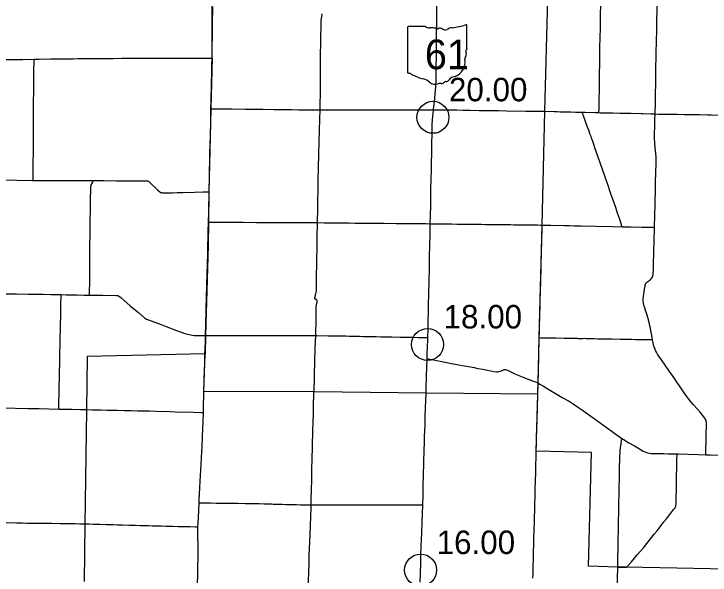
# Model space of a CAD drawing. Extents: x 1815539 to 1947826, y 273303 to 993194.
# Drawn here: x 1859353 to 1891996, y 939932 to 966222 of the extents above; entities that cross this region are included whole.
import ezdxf

# ---------------------------------------------------------------- set-up
doc = ezdxf.new("R2010")
doc.units = 0
for name, color, linetype in [('Default', 7, 'Continuous'), ('GM_X_County', 7, 'Continuous'), ('GM_X_County_Road', 7, 'Continuous'), ('GM_X_State_Route', 7, 'Continuous'), ('GM_X_Township', 7, 'Continuous'), ('GM_X_Township_Road', 7, 'Continuous'), ('SC_Shading3', 7, 'Continuous')]:
    doc.layers.add(name, color=color, linetype=linetype)

msp = doc.modelspace()

# ---------------------------------------------------------------- linework, layer by layer
at = {"layer": 'Default'}
for centre in [(1879002, 961378), (1878750, 950736), (1878424, 940166)]:
    msp.add_circle(centre, 750, dxfattribs=at)
at = {"layer": 'GM_X_County'}
msp.add_lwpolyline([(1855618, 964050), (1860298, 964101), (1862894, 964131), (1865546, 964151), (1868643, 964155), (1868654, 967077)], dxfattribs=at)
at = {"layer": 'GM_X_County_Road'}
for points in [[(1889424, 961538), (1889434, 962041), (1889441, 962402), (1889451, 963025), (1889459, 963534), (1889476, 964387), (1889485, 964945), (1889494, 965470), (1889503, 965962), (1889509, 966356), (1889517, 966733), (1889520, 966850)], [(1873708, 961725), (1873709, 961763), (1873716, 962074), (1873723, 962419), (1873727, 962615), (1873729, 962763), (1873731, 962878), (1873730, 963121), (1873729, 963301), (1873731, 963760), (1873732, 963957), (1873733, 964121), (1873736, 964432), (1873741, 964744), (1873749, 965219), (1873758, 965580), (1873761, 965760), (1873765, 965924), (1873772, 966006), (1873787, 966104), (1873814, 966232)], [(1868507, 957892), (1868508, 957985), (1868512, 958149), (1868517, 958378), (1868522, 958591), (1868529, 958936), (1868537, 959280), (1868545, 959706), (1868564, 960494), (1868580, 961199), (1868592, 961781)], [(1868592, 961781), (1868710, 961779), (1869580, 961768), (1870203, 961762), (1870531, 961757), (1870728, 961755), (1871023, 961753), (1871564, 961746), (1871991, 961742), (1872368, 961737), (1872696, 961735), (1873056, 961731), (1873679, 961725), (1873708, 961725)], [(1873585, 956443), (1873586, 956522), (1873597, 957030), (1873606, 957522), (1873614, 957899), (1873627, 958407), (1873639, 959030), (1873654, 959637), (1873668, 960227), (1873694, 961293), (1873708, 961725)], [(1873708, 961725), (1873925, 961725), (1874171, 961725), (1874400, 961725), (1874728, 961723), (1875040, 961721), (1875351, 961721), (1875696, 961724), (1876204, 961725), (1876483, 961726), (1876860, 961726), (1877139, 961727), (1877533, 961729), (1877959, 961730), (1878370, 961731), (1878730, 961731), (1878944, 961732), (1879031, 961735)], [(1879031, 961735), (1879064, 961735), (1879238, 961734), (1879550, 961729), (1880124, 961721), (1880403, 961717), (1880747, 961712), (1881174, 961704), (1881338, 961703), (1881584, 961698), (1881813, 961694), (1882059, 961692), (1882453, 961686), (1883355, 961673), (1883568, 961670), (1884011, 961664), (1884153, 961662)], [(1884153, 961662), (1884224, 961661), (1884683, 961649), (1884962, 961641), (1885257, 961632), (1885470, 961628), (1885683, 961622), (1885929, 961617), (1886003, 961615)], [(1886003, 961615), (1886142, 961612), (1886602, 961599), (1886785, 961597)], [(1886785, 961597), (1886848, 961596), (1887192, 961590), (1887438, 961582), (1887766, 961576), (1887979, 961573), (1888291, 961566), (1888832, 961553), (1889225, 961541), (1889305, 961540), (1889424, 961538)], [(1889391, 956223), (1889396, 956427), (1889399, 956591), (1889406, 956870), (1889414, 957214), (1889420, 957411), (1889433, 957936), (1889445, 958362), (1889457, 958772), (1889468, 959231), (1889469, 959411), (1889466, 959510), (1889452, 959690), (1889429, 959951), (1889412, 960180), (1889397, 960409), (1889393, 960540), (1889394, 960655), (1889402, 960901), (1889413, 961261), (1889424, 961538)], [(1889424, 961538), (1889576, 961533), (1889771, 961530), (1889984, 961529), (1890296, 961523), (1890476, 961521), (1890788, 961517), (1891263, 961507), (1891493, 961503), (1891870, 961495), (1892050, 961493)], [(1857510, 958468), (1857774, 958464), (1858381, 958450), (1859497, 958428), (1860219, 958415), (1860263, 958416)], [(1860263, 958416), (1860530, 958418), (1860648, 958417)], [(1860648, 958417), (1860798, 958416)], [(1860798, 958416), (1861285, 958413), (1861958, 958413), (1862450, 958411), (1862943, 958412), (1863078, 958412)], [(1863078, 958412), (1863583, 958411), (1864157, 958409), (1864698, 958408), (1865141, 958408), (1865552, 958407), (1865585, 958403), (1865618, 958396), (1865649, 958384), (1865677, 958366), (1865716, 958334), (1866089, 957988), (1866198, 957889), (1866237, 957861), (1866266, 957848), (1866297, 957840), (1866345, 957835), (1866476, 957837), (1866788, 957847), (1867000, 957854), (1867279, 957861), (1867821, 957876), (1868231, 957888), (1868411, 957892), (1868460, 957892), (1868507, 957892)], [(1868479, 956461), (1868488, 956919), (1868495, 957263), (1868503, 957624), (1868507, 957804), (1868507, 957892)], [(1868336, 951151), (1868350, 951655), (1868367, 952311), (1868372, 952508), (1868381, 952869), (1868400, 953541), (1868414, 954033), (1868438, 954984), (1868451, 955394), (1868459, 955722), (1868466, 956017), (1868479, 956461)], [(1873504, 951153), (1873507, 951263), (1873522, 951820), (1873526, 952181), (1873526, 952427), (1873531, 952509), (1873543, 952590), (1873576, 952734), (1873580, 952767), (1873579, 952783), (1873573, 952798), (1873563, 952811), (1873550, 952819), (1873504, 952838), (1873490, 952847), (1873479, 952859), (1873471, 952873), (1873466, 952889), (1873465, 952905), (1873466, 952921), (1873473, 952970), (1873501, 953082), (1873508, 953113), (1873523, 953177), (1873537, 953258), (1873542, 953324), (1873545, 953471), (1873549, 954029), (1873554, 954406), (1873557, 954668), (1873567, 955308), (1873574, 955751), (1873585, 956443)], [(1889186, 951564), (1889176, 951616), (1889143, 951760), (1889078, 951997), (1889044, 952106), (1888991, 952278), (1888936, 952450), (1888897, 952576), (1888877, 952655), (1888867, 952720), (1888863, 952785), (1888863, 952866), (1888872, 952996), (1888883, 953094), (1888918, 953321), (1888945, 953466), (1888959, 953530), (1888975, 953576), (1888991, 953604), (1889010, 953630), (1889034, 953653), (1889072, 953683), (1889167, 953746), (1889205, 953777), (1889240, 953812), (1889269, 953851), (1889292, 953894), (1889310, 953940), (1889319, 953972), (1889326, 954020), (1889332, 954102), (1889336, 954217), (1889343, 954462), (1889347, 954626), (1889355, 954921), (1889358, 955052), (1889363, 955216), (1889370, 955445), (1889374, 955642), (1889376, 955739), (1889386, 956018), (1889391, 956223)], [(1857535, 953123), (1857638, 953122), (1858590, 953112), (1859475, 953106), (1860033, 953098), (1860279, 953094), (1860722, 953087), (1861083, 953078), (1861561, 953071)], [(1861561, 953071), (1861804, 953066), (1862313, 953057), (1862625, 953053), (1862901, 953050)], [(1862901, 953050), (1863117, 953047), (1863527, 953043), (1864150, 953037), (1864199, 953033), (1864230, 953026), (1864258, 953013), (1864298, 952985), (1864359, 952931), (1864811, 952550), (1865212, 952211), (1865474, 951987), (1865525, 951946), (1865567, 951919), (1865612, 951899), (1866261, 951664), (1866491, 951578), (1866983, 951394), (1867244, 951296), (1867369, 951255), (1867496, 951221), (1867720, 951169), (1867801, 951156), (1867883, 951150), (1868113, 951149), (1868336, 951151)], [(1889295, 950966), (1889276, 951068), (1889201, 951487), (1889186, 951564)], [(1868310, 950179), (1868312, 950245), (1868329, 950852), (1868336, 951131), (1868336, 951151)], [(1873420, 948399), (1873426, 948591), (1873444, 949115), (1873451, 949345), (1873467, 949902), (1873486, 950558), (1873504, 951153)], [(1891793, 945572), (1891794, 945623), (1891802, 945902), (1891808, 946148), (1891811, 946295), (1891812, 946393), (1891815, 946524), (1891820, 946688), (1891823, 946819), (1891826, 947032), (1891825, 947098), (1891818, 947146), (1891804, 947193), (1891783, 947238), (1891758, 947280), (1891709, 947345), (1891527, 947557), (1891387, 947718), (1891225, 947903), (1891107, 948039), (1891003, 948166), (1890904, 948297), (1890782, 948471), (1890690, 948607), (1890534, 948838), (1890441, 948973), (1890338, 949121), (1890263, 949229), (1890097, 949473), (1889864, 949810), (1889639, 950132), (1889538, 950281), (1889477, 950379), (1889439, 950452), (1889400, 950542), (1889362, 950650), (1889341, 950729), (1889312, 950874), (1889295, 950966)], [(1868262, 948387), (1868281, 949097), (1868291, 949491), (1868302, 949884), (1868310, 950179)], [(1878728, 950072), (1878772, 950063), (1879110, 949997), (1879578, 949908), (1879949, 949836), (1880223, 949784), (1880384, 949754), (1880674, 949700), (1880932, 949650), (1881110, 949616), (1881335, 949574), (1881561, 949530), (1881851, 949473), (1881980, 949451), (1882013, 949449), (1882045, 949452), (1882093, 949464), (1882171, 949490), (1882246, 949522), (1882306, 949550), (1882337, 949560), (1882370, 949564), (1882402, 949562), (1882434, 949554), (1882494, 949527), (1882805, 949379), (1882957, 949317), (1883185, 949226), (1883629, 949054), (1883859, 948965), (1883918, 948938), (1883935, 948928)], [(1883920, 948423), (1883923, 948503), (1883924, 948585), (1883927, 948678), (1883930, 948781), (1883935, 948928)], [(1883935, 948928), (1884017, 948879), (1884184, 948775), (1884438, 948624), (1884664, 948490), (1885061, 948259), (1885389, 948072), (1885529, 947987), (1885774, 947821), (1886016, 947651), (1886256, 947481), (1886564, 947263), (1886671, 947186), (1886844, 947062), (1887017, 946936), (1887576, 946534), (1887803, 946372), (1887861, 946335)], [(1868239, 947536), (1868241, 947589), (1868248, 947851), (1868262, 948387)], [(1873289, 943219), (1873295, 943443), (1873306, 943951), (1873315, 944361), (1873327, 944968), (1873335, 945279), (1873351, 946017), (1873370, 946657), (1873384, 947132), (1873394, 947460), (1873401, 947739), (1873405, 947903), (1873420, 948399)], [(1883841, 945540), (1883841, 945543), (1883843, 945641), (1883846, 945734), (1883847, 945803), (1883848, 945863), (1883849, 945901), (1883850, 945959), (1883852, 946010), (1883854, 946068), (1883856, 946113), (1883857, 946159), (1883858, 946235), (1883859, 946286), (1883861, 946382), (1883863, 946474), (1883864, 946519), (1883871, 946699), (1883877, 946847), (1883878, 946929), (1883881, 947060), (1883886, 947175), (1883889, 947306), (1883892, 947421), (1883897, 947585), (1883900, 947716), (1883907, 947978), (1883912, 948137), (1883915, 948257), (1883918, 948355), (1883920, 948423)], [(1858837, 947762), (1860001, 947739), (1860542, 947729), (1861455, 947708)], [(1861455, 947708), (1861510, 947707), (1862067, 947697), (1862477, 947688), (1862762, 947682)], [(1862762, 947682), (1863002, 947677), (1863429, 947669), (1863724, 947662), (1864019, 947656), (1864216, 947653), (1864527, 947645), (1864855, 947638), (1865150, 947633), (1865708, 947620), (1866019, 947611), (1866675, 947590), (1866921, 947584), (1867774, 947557), (1868151, 947542), (1868200, 947538), (1868239, 947536)], [(1868039, 943315), (1868046, 943443), (1868077, 944017), (1868093, 944328), (1868137, 945114), (1868155, 945458), (1868181, 945933), (1868201, 946441), (1868226, 947130), (1868239, 947536)], [(1887666, 940305), (1887671, 940493), (1887678, 940805), (1887685, 941133), (1887690, 941428), (1887692, 941674), (1887698, 941937), (1887702, 942183), (1887707, 942511), (1887713, 942839), (1887719, 943200), (1887723, 943414), (1887728, 943594), (1887739, 944119), (1887744, 944365), (1887749, 944644), (1887757, 945038), (1887762, 945300), (1887766, 945514), (1887773, 945661), (1887783, 945776), (1887824, 946101), (1887843, 946248), (1887853, 946296), (1887861, 946335)], [(1887861, 946335), (1887928, 946292), (1888194, 946131), (1888449, 945981), (1888689, 945839), (1888860, 945742), (1888933, 945704), (1889008, 945672), (1889071, 945653), (1889136, 945641), (1889234, 945634), (1889825, 945622), (1890038, 945616), (1890452, 945608)], [(1883690, 939792), (1883694, 939939), (1883697, 940021), (1883701, 940202), (1883705, 940398), (1883711, 940611), (1883714, 940759), (1883717, 940907), (1883723, 941136), (1883725, 941267), (1883732, 941464), (1883733, 941530), (1883734, 941584), (1883736, 941648), (1883738, 941714), (1883740, 941775), (1883744, 941906), (1883748, 942021), (1883752, 942169), (1883756, 942300), (1883759, 942382), (1883763, 942480), (1883767, 942610), (1883770, 942708), (1883775, 942905), (1883779, 943020), (1883780, 943101), (1883782, 943216), (1883784, 943314), (1883786, 943380), (1883788, 943478), (1883792, 943625), (1883795, 943724), (1883802, 944019), (1883809, 944297), (1883811, 944412), (1883819, 944675), (1883822, 944806), (1883826, 944953), (1883831, 945117), (1883833, 945215), (1883835, 945314), (1883837, 945412), (1883841, 945540)], [(1888096, 940316), (1888102, 940320), (1888126, 940342), (1888158, 940380), (1888305, 940557), (1888455, 940731), (1888585, 940879), (1888886, 941226), (1888971, 941326), (1889101, 941495), (1889223, 941650), (1889375, 941844), (1889508, 942011), (1889651, 942191), (1889834, 942423), (1889946, 942564), (1890108, 942770), (1890304, 943013), (1890353, 943079), (1890377, 943122), (1890389, 943153), (1890398, 943201), (1890402, 943266), (1890405, 943463), (1890409, 943611), (1890415, 943906), (1890419, 944136), (1890429, 944645), (1890433, 944875), (1890444, 945383), (1890449, 945548), (1890452, 945608)], [(1890452, 945608), (1890497, 945607), (1890956, 945594), (1891432, 945581), (1891793, 945572)], [(1891793, 945572), (1892006, 945566), (1892728, 945552), (1892876, 945549), (1893352, 945535), (1893729, 945524), (1894221, 945511), (1894434, 945507), (1894492, 945506)], [(1867982, 942192), (1867989, 942379), (1868019, 942919), (1868039, 943315)], [(1872992, 935372), (1873017, 935986), (1873038, 936510), (1873045, 936691), (1873059, 937067), (1873073, 937395), (1873091, 937903), (1873111, 938411), (1873126, 938755), (1873146, 939296), (1873161, 939690), (1873175, 940034), (1873191, 940460), (1873205, 940853), (1873239, 941837), (1873254, 942230), (1873270, 942689), (1873285, 943082), (1873289, 943219)], [(1858756, 942397), (1858775, 942396), (1859005, 942391), (1859480, 942381), (1859759, 942376), (1859972, 942371), (1860267, 942366), (1860562, 942361), (1860789, 942359)], [(1860789, 942359), (1860890, 942358), (1861136, 942356), (1861514, 942352), (1861973, 942347), (1862202, 942343), (1862448, 942337), (1862661, 942334), (1862686, 942333)], [(1862686, 942333), (1862875, 942329), (1863088, 942323), (1863268, 942318), (1863383, 942314), (1863678, 942306), (1864022, 942296), (1864202, 942290), (1864448, 942284), (1864743, 942277), (1865055, 942268), (1865284, 942262), (1865448, 942258), (1865661, 942252), (1865842, 942246), (1866055, 942239), (1866268, 942235), (1866481, 942228), (1866809, 942220), (1867055, 942214), (1867284, 942207), (1867596, 942201), (1867875, 942194), (1867970, 942193), (1867982, 942192)], [(1867962, 939334), (1867968, 939541), (1867977, 939935), (1867982, 940214), (1867988, 940853), (1867986, 941296), (1867983, 941756), (1867982, 942182), (1867982, 942192)], [(1887613, 937674), (1887614, 937721), (1887621, 938130), (1887630, 938654), (1887634, 938932), (1887641, 939226), (1887666, 940305)], [(1887666, 940305), (1887714, 940305), (1887779, 940306), (1887943, 940298), (1888025, 940296), (1888058, 940300), (1888073, 940305), (1888088, 940311), (1888096, 940316)]]:
    msp.add_lwpolyline(points, dxfattribs=at)
at = {"layer": 'GM_X_State_Route'}
for points in [[(1879155, 963530), (1879156, 963565), (1879164, 964434), (1879170, 965041), (1879178, 965960), (1879189, 967078)], [(1879031, 961740), (1879088, 962255), (1879113, 962500), (1879134, 962794), (1879149, 963106), (1879155, 963530)], [(1878400, 939601), (1878426, 940454), (1878440, 940847), (1878456, 941290), (1878467, 941601), (1878478, 941912), (1878497, 942437), (1878511, 942797), (1878526, 943222), (1878527, 943240), (1878539, 943683), (1878550, 944142), (1878562, 944584), (1878578, 945207), (1878593, 945781), (1878604, 946142), (1878613, 946421), (1878630, 946961), (1878643, 947371), (1878654, 947732), (1878667, 948142), (1878676, 948404), (1878676, 948411), (1878685, 948699), (1878701, 949207), (1878717, 949716), (1878725, 949978), (1878728, 950072), (1878737, 950338), (1878745, 950568), (1878758, 950994), (1878760, 951058), (1878771, 951469), (1878781, 951895), (1878788, 952207), (1878795, 952568), (1878822, 953699), (1878835, 954257), (1878839, 954535), (1878845, 954781), (1878858, 955437), (1878865, 955798), (1878875, 956241), (1878878, 956392), (1878886, 956798), (1878895, 957208), (1878903, 957635), (1878910, 957979), (1878922, 958553), (1878927, 958815), (1878934, 959176), (1878945, 959766), (1878955, 960225), (1878960, 960521), (1878972, 961045), (1878980, 961242), (1878997, 961455), (1879026, 961692), (1879031, 961735), (1879031, 961740)]]:
    msp.add_lwpolyline(points, dxfattribs=at)
at = {"layer": 'GM_X_Township'}
for points in [[(1884254, 961672), (1884396, 966955), (1884454, 969588), (1884489, 972257), (1884586, 977269), (1884741, 982824), (1884889, 988110)], [(1841387, 963824), (1846780, 963929), (1847071, 963938), (1852487, 963992), (1853408, 964004), (1853786, 964009), (1855618, 964050), (1860298, 964101), (1862894, 964131), (1865546, 964151), (1868643, 964155), (1868586, 961770), (1868495, 957891), (1868480, 956467), (1868459, 955370), (1868335, 951151), (1868323, 950291), (1862794, 950174), (1862758, 947658), (1862681, 942300), (1862643, 939637)], [(1894401, 940177), (1888046, 940302), (1887975, 940298), (1887848, 940308), (1887664, 940306), (1886300, 940350), (1886440, 945673), (1883847, 945742), (1883913, 948407), (1883928, 948931), (1883977, 951060), (1884130, 956331), (1884254, 961672), (1886005, 961618), (1886788, 961599), (1889423, 961536), (1894728, 961453)], [(1883913, 948407), (1878685, 948461), (1873425, 948517), (1868265, 948533), (1868323, 950291)]]:
    msp.add_lwpolyline(points, dxfattribs=at)
at = {"layer": 'GM_X_Township_Road'}
for points in [[(1886785, 961597), (1886785, 961626), (1886789, 961756), (1886793, 961953), (1886797, 962182), (1886807, 962674), (1886811, 962985), (1886819, 963460), (1886826, 963852), (1886829, 964033), (1886828, 964697), (1886831, 964812), (1886842, 964956), (1886848, 965186), (1886852, 965497), (1886857, 965710), (1886859, 965923), (1886866, 966316), (1886870, 966513), (1886873, 966709), (1886874, 966824), (1886873, 966904)], [(1868650, 964156), (1868656, 964743), (1868661, 965120), (1868662, 965350), (1868668, 965744), (1868676, 966548)], [(1855601, 964061), (1855612, 964055), (1855624, 964052), (1855640, 964050), (1855755, 964047), (1856329, 964055), (1856608, 964056), (1856903, 964058), (1857526, 964065), (1858001, 964070), (1858591, 964078), (1858689, 964080), (1858755, 964080), (1858951, 964083), (1859771, 964094), (1860296, 964103)], [(1860263, 958416), (1860262, 958451), (1860261, 958532), (1860260, 958614), (1860260, 958695), (1860262, 958743), (1860262, 958792), (1860261, 958874), (1860260, 959415), (1860265, 959611), (1860265, 959857), (1860269, 960841), (1860275, 962038), (1860283, 962661), (1860289, 963170), (1860292, 963563), (1860297, 964006), (1860297, 964071), (1860296, 964103)], [(1860296, 964103), (1860542, 964106), (1861083, 964114), (1861837, 964122), (1862132, 964125), (1862345, 964127), (1862673, 964131), (1862893, 964133)], [(1862893, 964133), (1863132, 964135), (1863706, 964140), (1864001, 964140), (1864411, 964143), (1864952, 964147), (1865444, 964150), (1866084, 964152), (1866510, 964152), (1866838, 964152), (1867428, 964154), (1867838, 964154), (1868429, 964156), (1868650, 964156)], [(1868592, 961781), (1868599, 962100), (1868623, 962986), (1868632, 963429), (1868640, 963790), (1868650, 964156)], [(1886426, 960438), (1886414, 960472), (1886364, 960611), (1886338, 960689), (1886289, 960828), (1886272, 960874), (1886067, 961446), (1886020, 961569), (1886003, 961615)], [(1887492, 957377), (1887423, 957572), (1887314, 957882), (1887195, 958223), (1887074, 958581), (1886953, 958939), (1886861, 959203), (1886755, 959514), (1886662, 959777), (1886600, 959946), (1886507, 960209), (1886452, 960364), (1886426, 960438)], [(1862901, 953050), (1862901, 953090), (1862906, 953778), (1862908, 954155), (1862910, 954565), (1862916, 955237), (1862921, 956023), (1862927, 956384), (1862942, 957169), (1862947, 957448), (1862957, 958070), (1862963, 958136), (1862972, 958184), (1862982, 958215), (1863003, 958259), (1863051, 958345), (1863057, 958360), (1863078, 958412)], [(1887877, 956253), (1887866, 956283), (1887807, 956454), (1887742, 956640), (1887658, 956889), (1887570, 957154), (1887492, 957377)], [(1868479, 956461), (1868521, 956461), (1868915, 956462), (1869342, 956462), (1869621, 956461), (1870097, 956459), (1870720, 956456), (1870950, 956456), (1871589, 956451), (1872213, 956449), (1873000, 956446), (1873295, 956445), (1873585, 956443)], [(1873585, 956443), (1873607, 956443), (1873902, 956438), (1874132, 956437), (1874295, 956435), (1874656, 956432), (1875050, 956427), (1875362, 956426), (1875624, 956424), (1875887, 956422), (1876100, 956420), (1876346, 956415), (1876707, 956414), (1877281, 956410), (1877872, 956403), (1878429, 956399), (1878675, 956396), (1878872, 956392), (1878878, 956392)], [(1878878, 956392), (1879627, 956384), (1879873, 956382), (1880119, 956378), (1880660, 956372), (1880890, 956369), (1881185, 956366), (1881283, 956365), (1881463, 956364), (1881660, 956362), (1882086, 956357), (1882349, 956354), (1882644, 956350), (1882791, 956347), (1882955, 956346), (1883414, 956340), (1883677, 956337), (1883906, 956334), (1884022, 956333), (1884124, 956331)], [(1884029, 952612), (1884029, 952647), (1884035, 952876), (1884044, 953138), (1884049, 953335), (1884055, 953564), (1884063, 953793), (1884067, 953941), (1884070, 954121), (1884072, 954268), (1884077, 954481), (1884082, 954694), (1884087, 954874), (1884096, 955136), (1884099, 955251), (1884104, 955398), (1884112, 955709), (1884121, 956135), (1884124, 956299), (1884124, 956331)], [(1884124, 956331), (1884234, 956330), (1884530, 956323), (1885137, 956308), (1885399, 956304), (1885628, 956301), (1885957, 956294), (1886662, 956278), (1887416, 956263), (1887877, 956253)], [(1887877, 956253), (1887974, 956251), (1888302, 956248), (1888794, 956237), (1889072, 956232), (1889318, 956224), (1889391, 956223)], [(1861455, 947708), (1861456, 947742), (1861477, 948742), (1861487, 949185), (1861505, 950103), (1861521, 950955), (1861548, 952169), (1861553, 952447), (1861559, 952710), (1861562, 952923), (1861561, 953021), (1861561, 953071)], [(1883986, 951056), (1883994, 951320), (1883997, 951435), (1884001, 951615), (1884013, 952024), (1884020, 952237), (1884024, 952434), (1884029, 952612)], [(1868336, 951151), (1868396, 951151), (1869052, 951152), (1869463, 951153), (1870020, 951154), (1870693, 951153), (1870971, 951152), (1871447, 951150), (1871743, 951152), (1871988, 951153), (1872398, 951155), (1873136, 951154), (1873250, 951154), (1873504, 951153)], [(1873504, 951153), (1873578, 951153), (1874087, 951146), (1874382, 951144), (1874612, 951140), (1874923, 951136), (1875070, 951132), (1875218, 951127), (1875562, 951117), (1875726, 951113), (1875923, 951111), (1876119, 951107), (1876332, 951103), (1876562, 951098), (1876742, 951094), (1877070, 951089), (1877447, 951082), (1877661, 951079), (1877890, 951074), (1878038, 951071), (1878316, 951067), (1878562, 951062), (1878726, 951059), (1878760, 951058)], [(1883935, 948928), (1883938, 949076), (1883944, 949306), (1883954, 949716), (1883959, 949961), (1883963, 950125), (1883965, 950272), (1883966, 950469), (1883976, 950747), (1883986, 951056)], [(1883986, 951056), (1884045, 951054), (1884094, 951053), (1884356, 951049), (1884766, 951041), (1885160, 951034), (1885668, 951027), (1885767, 951024), (1885799, 951022), (1885962, 951020), (1886028, 951021), (1886110, 951024), (1886191, 951023), (1886272, 951019), (1886353, 951014), (1886419, 951012), (1886566, 951009), (1886730, 951006), (1886910, 951005), (1887025, 951004), (1887155, 951002), (1887270, 951001), (1887401, 950999), (1887794, 950992), (1887886, 950990)], [(1887886, 950990), (1888071, 950986), (1888202, 950984), (1888317, 950980), (1888497, 950975), (1888627, 950974), (1888939, 950971), (1889251, 950966), (1889295, 950966)], [(1868039, 943315), (1868058, 943315), (1868180, 943315), (1868360, 943313), (1868573, 943311), (1868836, 943307), (1869032, 943307), (1869229, 943304), (1869525, 943302), (1869853, 943298), (1870197, 943292), (1870362, 943289), (1870608, 943286), (1870854, 943283), (1871067, 943275), (1871297, 943267), (1871428, 943263), (1871510, 943261), (1871625, 943257), (1871756, 943253), (1871936, 943249), (1872100, 943245), (1872379, 943237), (1872609, 943234), (1872773, 943229), (1872843, 943228), (1872907, 943227), (1872971, 943226), (1873017, 943225), (1873083, 943224), (1873207, 943221), (1873289, 943219)], [(1873289, 943219), (1873306, 943219), (1873425, 943217), (1873521, 943216), (1873722, 943217), (1873886, 943218), (1874083, 943219), (1874247, 943221), (1874494, 943222), (1874608, 943224), (1874657, 943225), (1874723, 943225), (1874788, 943225), (1874862, 943224), (1874952, 943224), (1875046, 943223), (1875248, 943223), (1875320, 943223), (1875444, 943223), (1875543, 943223), (1875674, 943222), (1875822, 943221), (1876018, 943223), (1876183, 943223), (1876330, 943223), (1876494, 943223), (1876740, 943222), (1877019, 943222), (1877151, 943223), (1877413, 943224), (1877577, 943224), (1877659, 943224), (1877856, 943222), (1878119, 943222), (1878349, 943223), (1878430, 943223), (1878511, 943222), (1878526, 943222)]]:
    msp.add_lwpolyline(points, dxfattribs=at)
at = {"layer": 'SC_Shading3'}
for p, q in [((1877810, 965595), (1877810, 963482)), ((1878653, 965631), (1877837, 965631)), ((1880594, 964578), (1880594, 965684)), ((1880594, 964579), (1880594, 964578))]:
    msp.add_line(p, q, dxfattribs=at)
for centre, radius, start, end in [((1877842, 965600), 32.3, 98.1301, 188.1301), ((1878847, 965877), 313, 231.6195, 271.1119), ((1879602, 968513), 2953, 275.8445, 288.9065), ((1880563, 965688), 31, 351.8621, 97.738), ((1878951, 964445), 1123, 80.4867, 94.9883), ((1879206, 965611), 90.3, 219.7921, 297.1024), ((1879338, 965366), 188, 54.4667, 119.1411), ((1879580, 965701), 226, 233.8562, 294.8282), ((1879979, 964986), 594, 97.3462, 120.7689), ((1880587, 964497), 48, 107.944, 210.337), ((1880282, 964357), 288, 340.033, 23.6496), ((1880561, 964574), 33.2, 289.6038, 7.7341), ((1879768, 963975), 739, 292.3089, 8.9858), ((1880705, 964116), 210, 136.8065, 186.9296), ((1877842, 963477), 32.5, 171.9584, 258.3066), ((1877847, 963693), 248, 267.339, 280.6039), ((1877898, 963360), 89.5, 29.7484, 93.2717), ((1879028, 965259), 2132, 240.4129, 257.1985), ((1878393, 962532), 667, 47.1842, 75.836), ((1879114, 963349), 423, 230.7004, 286.2918), ((1879390, 963191), 226, 268.777, 315.5493), ((1879594, 962987), 63.5, 65.7517, 132.6484), ((1879567, 963277), 239, 282.8732, 323.2771), ((1880079, 962889), 404, 94.4031, 142.5768), ((1879359, 962619), 348, 85.6951, 111.2099)]:
    msp.add_arc(centre, radius, start, end, dxfattribs=at)

# ---------------------------------------------------------------- texts
at = {"layer": 'Default'}
for s, p in [('20.00', (1879752, 962128)), ('18.00', (1879500, 951486)), ('16.00', (1879174, 940916))]:
    msp.add_text(s, height=1100, dxfattribs=at).set_placement(p)
at = {"layer": 'SC_Shading3'}
msp.add_text('61', height=1392.2, dxfattribs=at).set_placement((1878620, 963631))

doc.saveas('drawing.dxf')
